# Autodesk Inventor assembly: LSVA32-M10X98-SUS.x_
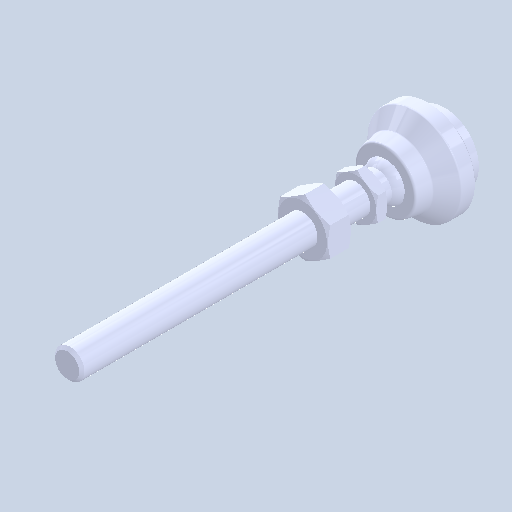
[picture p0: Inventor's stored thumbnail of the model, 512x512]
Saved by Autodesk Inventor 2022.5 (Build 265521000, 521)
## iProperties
Created: 2024-08
Part Number: LSVA32-M10X98-SUS.x_
Document SubType Name: Assembly
Designer: ImaoCorp
Author: ImaoCorp
Sending System: SOLIDWORKS 2022-2022290
MC: AMD64
MC_MODEL: Intel64 Family 6 Model 60 Stepping 3, GenuineIntel
OS: Windows_NT
FRU: Parasolid Version 33.1, build 260,  4-25-2022
FORMAT: text
GUISE: transmit
KEY: FILELSVA32-M10X98-SUS.x_t
DATE: Fri Aug 23 16:06:30 2024
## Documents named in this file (4)
- X:\14_SW2022-Inv2022\06_2024-10新製品(SME)\ELS_データ\l\lsva32-m10x98-sus\LSVA32-M10X98-SUS.x_.iam
- X:\14_SW2022-Inv2022\06_2024-10新製品(SME)\ELS_データ\l\lsva32-m10x98-sus\LSVA32-M10X98-SUS_01.ipt
- X:\14_SW2022-Inv2022\06_2024-10新製品(SME)\ELS_データ\l\lsva32-m10x98-sus\LSVA32-M10X98-SUS_02.ipt
- X:\14_SW2022-Inv2022\06_2024-10新製品(SME)\ELS_データ\l\lsva32-m10x98-sus\LSVA32-M10X98-SUS_03.ipt
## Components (3 placed, 3 different names)
1. LSVA32-M10X98-SUS_01
2. LSVA32-M10X98-SUS_02
3. LSVA32-M10X98-SUS_03
